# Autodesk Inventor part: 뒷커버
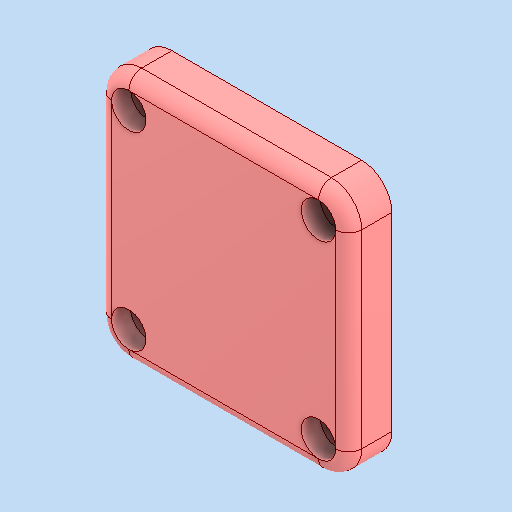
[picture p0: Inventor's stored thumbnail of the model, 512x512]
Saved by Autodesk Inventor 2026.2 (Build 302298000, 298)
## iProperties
Created: 2026-01
Part Number: 뒷커버
Material: 알루미늄 6061
Document SubType Name: Modeling
Designer: PC2-07
Density: 2.7 g/cm^3
Appearance: 기본값
Author: jhkim
Sending System: Autodesk Inventor 2026
Preprocessor: ST-DEVELOPER v20.1
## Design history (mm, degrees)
feature "솔리드1"
node "솔리드2"
